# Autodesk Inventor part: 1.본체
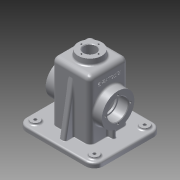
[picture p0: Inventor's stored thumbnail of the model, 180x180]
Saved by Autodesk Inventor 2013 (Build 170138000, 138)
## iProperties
Created: 2016-01
Part Number: 1.본체
Material: 알루미늄 6061
Document SubType Name: Modeling
Designer: Administrator
Density: 2.71 g/cm^3
Mass: 807.488 g
Surface Area: 908.64 cm^2
Volume: 297.966 cm^3
Author: Administrator
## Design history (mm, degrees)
sketch "스케치1"
  geometry: L1 (-65, 57.5)-(65, 57.5); L2 (65, 57.5)-(65, -57.5); L3 (65, -57.5)-(-65, -57.5); L4 (-65, -57.5)-(-65, 57.5); 3 further points
  constraints: 8 end point, 2 midpoint, 2 parallel, 1 horizontal, 1 horizontal alignment, 1 perpendicular, 1 vertical alignment
  dimensions: "d0" = 130 distance of L2.end L3.end; "d2" = 115 distance of L1.end L2.end
extrude "돌출1" new body sketch "스케치1" distance "d3" = 8; taper "d4" = 0 deg
sketch "스케치2"
  geometry: L1 (65, 57.5)-(-65, 57.5) reference; L2 (-65, 57.5)-(-65, -57.5) reference; L3 (-65, -57.5)-(65, -57.5) reference; L4 (65, -57.5)-(65, 57.5) reference; L5 (-60, -52.5)-(-60, 52.5); L6 (-60, 52.5)-(60, 52.5); L7 (60, 52.5)-(60, -52.5); L8 (60, -52.5)-(-60, -52.5); 1 further point
  constraints: 8 end point, 3 other
  dimensions: "d5" = 5 distance between parallel lines of L3 L8
extrude "돌출2" join sketch "스케치2" distance "d6" = 2; taper "d7" = 0 deg
sketch "스케치3"
  geometry: L1 (-32.5, 32.5)-(32.5, 32.5); L2 (32.5, 32.5)-(32.5, -32.5); L3 (32.5, -32.5)-(-32.5, -32.5); L4 (-32.5, -32.5)-(-32.5, 32.5); 3 further points
  constraints: 8 end point, 2 midpoint, 2 parallel, 1 horizontal, 1 horizontal alignment, 1 perpendicular, 1 vertical alignment
  dimensions: "d8" = 65 distance of L3.end L1.start; "d10" = 65 distance of L1.start L1.end
extrude "돌출3" join sketch "스케치3" distance "d11" = 100; taper "d12" = 0 deg
sketch "스케치4"
  geometry: L1 (-27.5, -27.5)-(27.5, -27.5); L2 (27.5, -27.5)-(27.5, 27.5); L3 (27.5, 27.5)-(-27.5, 27.5); L4 (-27.5, 27.5)-(-27.5, -27.5); 3 further points
  constraints: 8 end point, 2 midpoint, 2 parallel, 1 horizontal, 1 horizontal alignment, 1 perpendicular, 1 vertical alignment
  dimensions: "d13" = 55 distance of L3.end L1.start; "d15" = 55 distance of L1.start L1.end
extrude "돌출4" cut sketch "스케치4" distance "d16" = 105; taper "d17" = 0 deg
node "작업 평면1"
sketch "스케치5"
  geometry: C1 r 20 at (0, 0); 1 further point
  constraints: 1 centre point, 1 coincident
  dimensions: "d19" = 40 diameter of C1
extrude "돌출5" join sketch "스케치5" stored distance "d20" = 105; taper "d21" = 0 deg
hole "구멍1" diameter "d24" = 21; stored, may be unused: countersink angle "d28" = 90 deg, drill point angle "d30" = 118 deg; dims "d22" = 10, "d23" = 10, "d25" = 6, "d26" = 4, "d27" = 2, "d29" = 23
node "작업 평면3"
sketch "스케치6"
  geometry: L1 (10, 5)-(10, 60) reference; C1 r 27.5 at (-45, 32.5); 1 further point
  constraints: 1 centre point, 1 horizontal alignment
  dimensions: "d32" = 55 distance from line of C1.centre L1; "d33" = 55 diameter of C1
extrude "돌출6" join sketch "스케치6" stored distance "d34" = 105; taper "d35" = 0 deg
hole "구멍2" diameter "d38" = 30; stored, may be unused: countersink angle "d42" = 90 deg, drill point angle "d44" = 0 deg; dims "d36" = 10, "d37" = 10, "d39" = 6, "d40" = 35, "d41" = 17, "d43" = 23
feature "면 기울기1" dims angle "d45" = 5 deg
sketch "스케치7"
  geometry: L1 (-42.5, 25.5)-(-42.5, 8); L2 (20, 118)-(20.875, 108) reference; L3 (20.875, 108)-(32.5, 108) reference; L4 (32.5, 108)-(32.5, 80.5) reference; L5 (32.5, 80.5)-(47.5, 80.5) reference; L6 (47.5, 80.5)-(47.5, 70.5) reference; L7 (47.5, 70.5)-(30.5, 70.5) reference; L8 (30.5, 70.5)-(30.5, 68) reference; L9 (30.5, 68)-(27.5, 68) reference; L10 (27.5, 68)-(27.5, 103) reference; L11 (27.5, 103)-(10.5, 103) reference; L12 (10.5, 103)-(10.5, 118) reference; L13 (10.5, 118)-(20, 118) reference; L14 (-20.875, 108)-(-20, 118) reference; L15 (-20, 118)-(-10.5, 118) reference; L16 (-10.5, 118)-(-10.5, 103) reference; L17 (-10.5, 103)-(-27.5, 103) reference; L18 (-27.5, 103)-(-27.5, 68) reference; L19 (-27.5, 68)-(-30.5, 68) reference; L20 (-30.5, 68)-(-30.5, 70.5) reference; L21 (-30.5, 70.5)-(-47.5, 70.5) reference; L22 (-47.5, 70.5)-(-47.5, 80.5) reference; L23 (-47.5, 80.5)-(-32.5, 80.5) reference; L24 (-32.5, 80.5)-(-32.5, 108) reference; L25 (-32.5, 108)-(-20.875, 108) reference; L26 (-65, 0)-(-65, 8) reference; L27 (-65, 8)-(-32.5, 8) reference; L28 (-32.5, 8)-(-32.5, 25.5) reference; L29 (-32.5, 25.5)-(-47.5, 25.5) reference; L30 (-47.5, 25.5)-(-47.5, 35.5) reference; L31 (-47.5, 35.5)-(-30.5, 35.5) reference; L32 (-30.5, 35.5)-(-30.5, 38) reference; L33 (-30.5, 38)-(-27.5, 38) reference; L34 (-27.5, 38)-(-27.5, -2) reference; L35 (-27.5, -2)-(-60, -2) reference; L36 (-60, -2)-(-60, 0) reference; L37 (-60, 0)-(-65, 0) reference; L38 (65, 8)-(65, 0) reference; L39 (65, 0)-(60, 0) reference; L40 (60, 0)-(60, -2) reference; L41 (60, -2)-(27.5, -2) reference; L42 (27.5, -2)-(27.5, 38) reference; L43 (27.5, 38)-(30.5, 38) reference; L44 (30.5, 38)-(30.5, 35.5) reference; L45 (30.5, 35.5)-(47.5, 35.5) reference; L46 (47.5, 35.5)-(47.5, 25.5) reference; L47 (47.5, 25.5)-(32.5, 25.5) reference; L48 (32.5, 25.5)-(32.5, 8) reference; L49 (32.5, 8)-(65, 8) reference; 1 further point
  constraints: 2 end point, 2 horizontal alignment, 1 vertical
  dimensions: "d46" = 15 distance between parallel lines of L1 L34
feature "리브1" sketch "스케치7" dims "d47" = 1, "d48" = 6, "d49" = 0, "d50" = 0, "d51" = 1, "d52" = 1
sketch "스케치8"
  geometry: L1 (-32.5, 108)-(-20.875, 108) reference; L2 (-20.875, 108)-(-20, 118) reference; L3 (-20, 118)-(-10.5, 118) reference; L4 (-10.5, 118)-(-10.5, 103) reference; L5 (-10.5, 103)-(-27.5, 103) reference; L6 (-27.5, 103)-(-27.5, -2) reference; L7 (-27.5, -2)-(-52.5, -2) reference; L8 (-52.5, -2)-(-52.5, 0) reference; L9 (-52.5, 0)-(-57.5, 0) reference; L10 (-57.5, 0)-(-57.5, 8) reference; L11 (-57.5, 8)-(-32.5, 8) reference; L12 (-32.5, 8)-(-32.5, 108) reference; L13 (20.875, 108)-(32.5, 108) reference; L14 (32.5, 108)-(32.5, 8) reference; L15 (32.5, 8)-(57.5, 8) reference; L16 (57.5, 8)-(57.5, 0) reference; L17 (57.5, 0)-(52.5, 0) reference; L18 (52.5, 0)-(52.5, -2) reference; L19 (52.5, -2)-(27.5, -2) reference; L20 (27.5, -2)-(27.5, 103) reference; L21 (27.5, 103)-(10.5, 103) reference; L22 (10.5, 103)-(10.5, 118) reference; L23 (10.5, 118)-(20, 118) reference; L24 (20, 118)-(20.875, 108) reference; L25 (-47.5, 8)-(-32.5, 93.069); 1 further point
  constraints: 2 end point, 2 point on line
  dimensions: "d54" = 10 deg angle of L25 L10; "d55" = 10 distance of L10.end L25.start
feature "리브2" sketch "스케치8" dims "d56" = 1, "d57" = 10, "d58" = 0, "d59" = 0, "d60" = 1, "d61" = 1
fillet "모깎기1" dims "d62" = 15
sketch "스케치9"
  geometry: C1 r 7.5 at (-50, 42.5); A1 r 15 centre (-50, 42.5) between (-50, 57.5) and (-65, 42.5) reference; 1 further point
  constraints: 1 centre point, 1 coincident
  dimensions: "d63" = 15 diameter of C1
extrude "돌출7" join sketch "스케치9" distance "d64" = 3; taper "d65" = 0 deg
hole "구멍3" diameter "d68" = 5; stored, may be unused: countersink angle "d72" = 90 deg, drill point angle "d74" = 0 deg; dims "d66" = 10, "d67" = 10, "d69" = 6, "d70" = 35, "d71" = 17, "d73" = 23
fillet "모깎기2" dims "d81" = 8
fillet "모깎기3" dims "d82" = 8
fillet "모깎기4" dims "d83" = 3
fillet "모깎기5" dims "d84" = 3
fillet "모깎기6" dims "d85" = 3
fillet "모깎기7" dims "d86" = 3
fillet "모깎기8" dims "d87" = 1
sketch "스케치10"
  geometry: C1 r 17.5 at (0, 0) reference; 2 further points
  constraints: 1 horizontal alignment
  dimensions: "d88" = 21 distance of C1.centre point (-21, 0)
hole "구멍4" sketch "스케치10" at (-21, 0) diameter "d89" = 3.242; stored, may be unused: countersink angle "d93" = 90 deg, drill point angle "d95" = 118 deg; dims "d90" = 8, "d91" = 35, "d92" = 17, "d94" = 10
sketch "스케치11"
  geometry: C1 r 10.5 at (0, 0) reference; 1 further point
  constraints: 1 vertical alignment
  dimensions: "d99" = 14.5 distance of point (0, 14.5) C1.centre
hole "구멍5" sketch "스케치11" at (0, 14.5) diameter "d100" = 2.459; stored, may be unused: countersink angle "d104" = 90 deg, drill point angle "d106" = 118 deg; dims "d101" = 7, "d102" = 35, "d103" = 17, "d105" = 9
fillet "모깎기9" dims "d110" = 3
fillet "모깎기10" dims "d111" = 10
fillet "모깎기11" dims "d112" = 0.3
chamfer "모따기1" distance "d113" = 1; stored, may be unused: second distance "d114" = 2, angle "d115" = 45 deg
sketch "스케치12"
  geometry: L1 (-18, 4.5)-(-18, 44.5) reference; A1 r 30.5 centre (47, 24.5) between (28.834, 49) and (28.834, 0) reference; 2 further points
  constraints: 1 horizontal alignment, 1 other
  dimensions: "d116" = 27 distance from line of point (9, 24.5) L1
feature "엠보싱1" sketch "스케치12" dims "d117" = 0.5, "d118" = 0
fillet "모깎기12" dims "d119" = 3
node "솔리드1"
mirror "대칭2"
mirror "대칭3"
mirror "대칭4"
pattern_linear "직사각형 패턴1" dims "d77" = 85
pattern_circular "원형 패턴1" dims angle "d97" = 360 deg
mirror "대칭5"
pattern_circular "원형 패턴2" dims angle "d108" = 360 deg
node "절단 모서리 투영1"
node "절단 모서리 투영2"
other parameters: "d31" = 15
